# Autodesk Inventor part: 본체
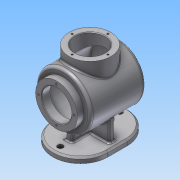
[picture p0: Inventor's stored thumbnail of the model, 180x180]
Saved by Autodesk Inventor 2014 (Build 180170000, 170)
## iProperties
Created: 2016-04
Part Number: 본체
Material: 알루미늄 6061
Document SubType Name: Modeling
Designer: 601-
Density: 2.71 g/cm^3
Appearance: 알루미늄 - 평지
Mass: 912.465 g
Surface Area: 1227.11 cm^2
Volume: 336.703 cm^3
Author: 601-
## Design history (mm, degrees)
sketch "스케치1"
  geometry: L1 (0, -67.5)-(0, -67.5); L2 (50, -17.5)-(50, 17.5); L3 (0, 67.5)-(0, 67.5); L4 (-50, 17.5)-(-50, -17.5); L5 (-50, -67.5)-(50, 67.5); L6 (50, -67.5)-(-50, 67.5); A1 r 2 centre (-48, 65.5) between (-48, 67.5) and (-50, 65.5); A2 r 50 centre (0, 17.5) between (0, 67.5) and (-50, 17.5); A3 r 50 centre (0, 17.5) between (50, 17.5) and (0, 67.5); A4 r 50 centre (0, -17.5) between (0, -67.5) and (50, -17.5); A5 r 50 centre (0, -17.5) between (-50, -17.5) and (0, -67.5); 1 further point
  constraints: 12 end point, 10 point on circle, 10 point on line, 10 tangent, 5 centre point, 3 equal radius, 2 midpoint, 2 parallel, 1 horizontal, 1 perpendicular
  dimensions: "d0" = 100 distance of L5.end L6.end; "d1" = 135 distance of L6.end L5.start; "d2" = 2 radius of A1; "d3" = 50 radius of A2
extrude "돌출1" new body sketch "스케치1" distance "d4" = 10; taper "d5" = 0 deg
sketch "스케치2"
  geometry: L1 (50, -17.5)-(50, 17.5) reference; L2 (0, 0)-(0, 54); C1 r 5 at (0, 54)
  constraints: 2 end point, 1 centre point, 1 coincident, 1 parallel
  dimensions: "d6" = 54 distance of L2.start L2.end; "d7" = 10 diameter of C1
extrude "돌출2" cut sketch "스케치2" distance "d8" = 10; taper "d9" = 0 deg
sketch "스케치3" dims "d11" = 100
  geometry: L1 (0, 0)-(0, 79); L2 (0, 79)-(0, 129); 1 further point
  constraints: 4 end point, 2 coincident, 1 collinear, 1 vertical, 1 vertical alignment, 2 other
  dimensions: "d10" = 79 distance of L1.start L1.end
extrude "돌출3" join sketch "스케치3" stored distance "d12" = 122; taper "d13" = 0 deg
sketch "스케치5"
  geometry: C1 r 50 at (0, 0) reference; C2 r 38 at (0, 0); C3 r 50 at (0, 0); 1 further point
  constraints: 2 centre point, 2 coincident
  dimensions: "d17" = 76 diameter of C2; "d18" = 100 diameter of C3
extrude "돌출4" cut sketch "스케치5" distance "d19" = 12; taper "d20" = 0 deg
sketch "스케치6"
  geometry: L1 (61, 29)-(61, 129) reference; L2 (61, 79)-(61, 155.568); L3 (50.087, 129)-(50.087, 29); L4 (61, 79)-(50.087, 79); L5 (50.087, 129)-(61, 129); L6 (-49, 129)-(61, 129) reference; L7 (50.087, 29)-(61, 29); L8 (-49, 29)-(61, 29) reference; L9 (61, 79)-(50.087, 79); A1 r 120 centre (-59, 79) between (61, 79) and (50.087, 129); 1 further point
  constraints: 12 end point, 4 collinear, 2 midpoint, 2 point on circle, 1 centre point, 1 parallel, 1 tangent
  dimensions: "d21" = 240 diameter of A1
revolve "회전1" stored, may be unused: angle "d22" = 90 deg
revolve "회전2" stored, may be unused: angle "d23" = 90 deg
sketch "스케치11"
  geometry: L1 (0, 0)-(-40, 0); L2 (-17.5, 0)-(-67.5, 0) reference; L3 (-40, 0)-(-30.035, 56.516); L4 (-30.035, 56.516)-(30.035, 56.516); L5 (30.035, 56.516)-(40, 0); L6 (40, 0)-(0, 0); L7 (67.5, 0)-(17.5, 0) reference
  constraints: 10 end point, 2 parallel, 1 point on line
  dimensions: "d27" = 40 distance of L1.start L1.end; "d28" = 100 deg angle of L3 L2; "d29" = 40 distance of L5.end L1.start; "d30" = 100 deg angle of L7 L5
extrude "돌출5" join sketch "스케치11" stored distance "d31" = 10; taper "d32" = 0 deg
sketch "스케치12"
  geometry: L1 (0, 0)-(-40, 0); L2 (50, 0)-(-50, 0) reference; L3 (-40, 0)-(-40, 64.037); L4 (-40, 64.037)-(40, 64.037); L5 (40, 64.037)-(40, 0); L6 (40, 0)-(0, 0)
  constraints: 10 end point, 3 perpendicular, 2 point on line, 1 collinear
  dimensions: "d33" = 40 distance of L1.start L1.end; "d34" = 40 distance of L5.end L1.start
extrude "돌출6" join sketch "스케치12" stored distance "d35" = 10; taper "d36" = 0 deg
node "작업 평면2"
sketch "스케치17"
  geometry: C1 r 38 at (0, 0); 1 further point
  constraints: 1 centre point, 1 coincident
  dimensions: "d39" = 76 diameter of C1
extrude "돌출7" join sketch "스케치17" distance "d40" = 50; taper "d41" = 0 deg
chamfer "모따기1" distance "d42" = 3; stored, may be unused: second distance "d43" = 2, angle "d44" = 45 deg
sketch "스케치18"
  geometry: C1 r 38 at (0, 0) reference; C2 r 27 at (0, 0); 1 further point
  constraints: 1 centre point, 1 coincident
  dimensions: "d45" = 54 diameter of C2
sketch "스케치19"
  geometry: L1 (47.95, 125.951)-(47.95, 79); L2 (47.95, 79)-(57.495, 79); A1 r 117 centre (-59.503, 79.66) between (47.385, 32.078) and (50.087, 38.684); A2 r 47 centre (50.087, 79) between (47.385, 32.078) and (50.087, 32); A3 r 117 centre (-59.503, 79.66) between (57.495, 79) and (47.95, 125.951); 1 further point
  constraints: 6 point on circle, 4 end point, 3 centre point, 1 coincident, 1 perpendicular
  dimensions: "d49" = 234 diameter of A3
revolve "회전3" sketch "스케치19" stored, may be unused: angle "d50" = 90 deg
sketch "스케치20"
  geometry: L1 (-49, 117)-(-49, 41) reference; L2 (-46, 78.951)-(47.95, 79); L3 (-46, 78.951)-(-46, 126); L4 (-46, 126)-(47.95, 125.951); L5 (-46, 125.951)-(-46, 78.951); L6 (47.95, 125.951)-(47.95, 79); 1 further point
  constraints: 10 end point, 1 collinear, 1 point on line
  dimensions: "d64" = 93.95003 distance of L3.end L4.end
revolve "회전4" sketch "스케치20" stored, may be unused: angle "d65" = 90 deg
sketch "스케치22"
  geometry: C1 r 38 at (0, 0) reference; C2 r 27 at (0, 0); 1 further point
  constraints: 1 centre point, 1 coincident
  dimensions: "d66" = 54 diameter of C2
extrude "돌출8" cut sketch "스케치22" distance "d67" = 50; taper "d68" = 0 deg
sketch "스케치23"
  geometry: C1 r 38 at (0, 0) reference; C2 r 27 at (0, 0)
  constraints: 1 centre point, 1 coincident
  dimensions: "d69" = 54 diameter of C2
extrude "돌출9" cut sketch "스케치23" distance "d70" = 50; taper "d71" = 0 deg
sketch "스케치24" dims "d72" = 65
  geometry: L1 (0, 0)-(0, 32.5); C1 r 38 at (0, 0) reference; 2 further points
  constraints: 2 coincident, 2 end point, 1 vertical, 1 vertical alignment, 2 other
hole "구멍1" sketch "스케치24" at (0, 32.5) diameter "d73" = 3.242; stored, may be unused: countersink angle "d77" = 90 deg, drill point angle "d79" = 118 deg; dims "d74" = 8, "d75" = 4, "d76" = 2, "d78" = 10
sketch "스케치25" dims "d83" = 65
  geometry: L1 (0, 0)-(0, 32.5); C1 r 38 at (0, 0) reference; 1 further point
  constraints: 2 coincident, 2 end point, 1 vertical, 1 vertical alignment, 2 other
hole "구멍2" sketch "스케치25" at (0, 32.5) diameter "d84" = 3.242; stored, may be unused: countersink angle "d88" = 90 deg, drill point angle "d90" = 118 deg; dims "d85" = 8, "d86" = 4, "d87" = 2, "d89" = 10
chamfer "모따기2" distance "d94" = 1; stored, may be unused: second distance "d95" = 2, angle "d96" = 45 deg
fillet "모깎기1" dims "d97" = 5
fillet "모깎기2" dims "d98" = 5
fillet "모깎기3" dims "d99" = 2
fillet "모깎기4" dims "d100" = 3
fillet "모깎기5" dims "d101" = 2
fillet "모깎기6" dims "d102" = 3
node "솔리드1"
mirror "대칭1"
pattern_circular "원형 패턴1" dims angle "d81" = 360 deg
pattern_circular "원형 패턴2" dims angle "d92" = 360 deg
other parameters: "d38" = -144, "d48" = 94
